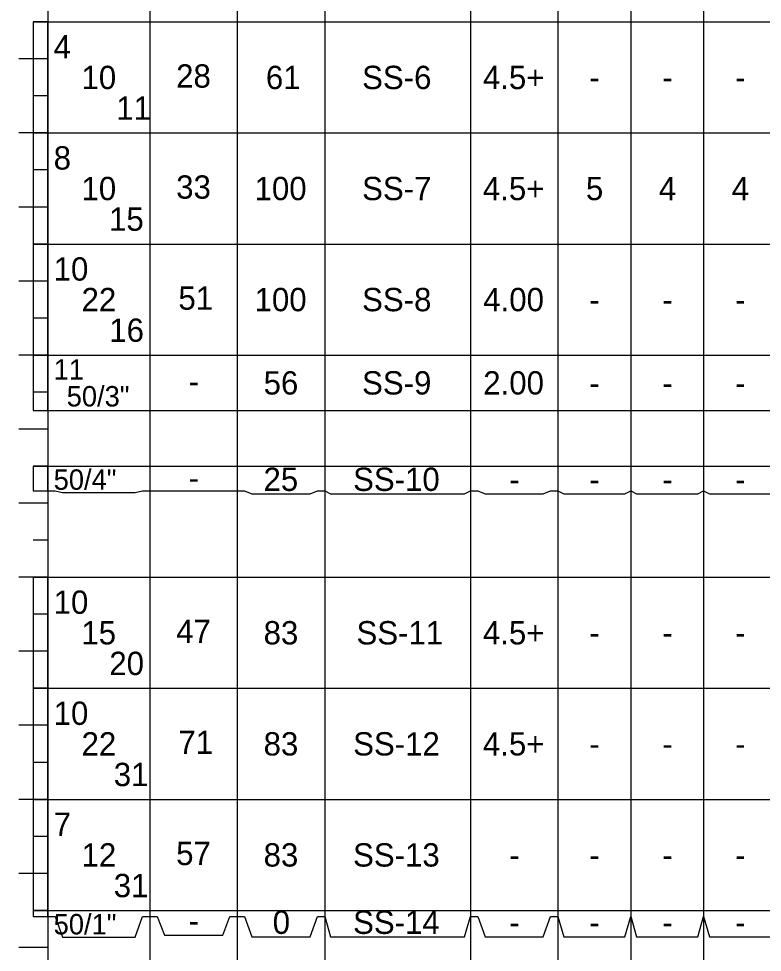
# Model space of a CAD drawing. Extents: x 0 to 0.833, y -0.323 to 0.608.
# Drawn here: x 0.4042 to 0.6168, y 0.0833 to 0.3502 of the extents above; entities that cross this region are included whole.
import ezdxf

# ---------------------------------------------------------------- set-up
doc = ezdxf.new("R2010")
doc.units = 0

msp = doc.modelspace()

# ---------------------------------------------------------------- linework, layer by layer
for points in [[(0.4125, 0.55417), (0.4125, -0.28575)], [(0.4125, 0.55417), (0.4125, -0.28575)], [(0.44167, 0.55417), (0.44167, -0.28575)], [(0.46667, 0.55417), (0.46667, -0.28575)], [(0.49167, 0.55417), (0.49167, -0.28575)], [(0.53333, 0.55417), (0.53333, -0.28575)], [(0.55833, 0.55417), (0.55833, -0.28575)], [(0.57917, 0.54167), (0.57917, -0.28575)], [(0.6, 0.54167), (0.6, -0.28575)], [(0.40833, 0.34925), (0.40833, 0.3175)], [(0.40833, 0.34925), (0.4125, 0.34925)], [(0.4125, 0.34925), (0.40833, 0.34925)], [(0.4125, 0.34925), (0.44167, 0.34925)], [(0.44167, 0.34925), (0.46667, 0.34925)], [(0.46667, 0.34925), (0.49167, 0.34925)], [(0.49167, 0.34925), (0.53333, 0.34925)], [(0.53333, 0.34925), (0.55833, 0.34925)], [(0.55833, 0.34925), (0.57917, 0.34925)], [(0.57917, 0.34925), (0.6, 0.34925)], [(0.6, 0.34925), (0.62083, 0.34925)], [(0.4125, 0.33867), (0.40417, 0.33867)], [(0.4125, 0.33867), (0.40833, 0.33867)], [(0.4125, 0.32808), (0.40833, 0.32808)], [(0.4125, 0.3175), (0.40417, 0.3175)], [(0.40833, 0.3175), (0.4125, 0.3175)], [(0.40833, 0.3175), (0.40833, 0.28575)], [(0.40833, 0.3175), (0.4125, 0.3175)], [(0.4125, 0.3175), (0.40833, 0.3175)], [(0.4125, 0.3175), (0.44167, 0.3175)], [(0.44167, 0.3175), (0.46667, 0.3175)], [(0.46667, 0.3175), (0.49167, 0.3175)], [(0.49167, 0.3175), (0.53333, 0.3175)], [(0.53333, 0.3175), (0.55833, 0.3175)], [(0.55833, 0.3175), (0.57917, 0.3175)], [(0.57917, 0.3175), (0.6, 0.3175)], [(0.6, 0.3175), (0.62083, 0.3175)], [(0.4125, 0.30692), (0.40833, 0.30692)], [(0.4125, 0.29633), (0.40417, 0.29633)], [(0.4125, 0.29633), (0.40833, 0.29633)], [(0.40833, 0.28575), (0.4125, 0.28575)], [(0.40833, 0.28575), (0.40833, 0.254)], [(0.40833, 0.28575), (0.4125, 0.28575)], [(0.4125, 0.28575), (0.40833, 0.28575)], [(0.4125, 0.28575), (0.44167, 0.28575)], [(0.44167, 0.28575), (0.46667, 0.28575)], [(0.46667, 0.28575), (0.49167, 0.28575)], [(0.49167, 0.28575), (0.53333, 0.28575)], [(0.53333, 0.28575), (0.55833, 0.28575)], [(0.55833, 0.28575), (0.57917, 0.28575)], [(0.57917, 0.28575), (0.6, 0.28575)], [(0.6, 0.28575), (0.62083, 0.28575)], [(0.4125, 0.27517), (0.40417, 0.27517)], [(0.4125, 0.27517), (0.40833, 0.27517)], [(0.4125, 0.26458), (0.40833, 0.26458)], [(0.4125, 0.254), (0.40417, 0.254)], [(0.40833, 0.254), (0.4125, 0.254)], [(0.40833, 0.254), (0.40833, 0.23812)], [(0.40833, 0.254), (0.4125, 0.254)], [(0.4125, 0.254), (0.40833, 0.254)], [(0.4125, 0.254), (0.44167, 0.254)], [(0.44167, 0.254), (0.46667, 0.254)], [(0.46667, 0.254), (0.49167, 0.254)], [(0.49167, 0.254), (0.53333, 0.254)], [(0.53333, 0.254), (0.55833, 0.254)], [(0.55833, 0.254), (0.57917, 0.254)], [(0.57917, 0.254), (0.6, 0.254)], [(0.6, 0.254), (0.62083, 0.254)], [(0.4125, 0.24342), (0.40833, 0.24342)], [(0.40833, 0.23812), (0.4125, 0.23812)], [(0.4125, 0.23812), (0.44167, 0.23812)], [(0.44167, 0.23812), (0.46667, 0.23812)], [(0.46667, 0.23812), (0.49167, 0.23812)], [(0.49167, 0.23812), (0.53333, 0.23812)], [(0.53333, 0.23812), (0.55833, 0.23812)], [(0.55833, 0.23812), (0.57917, 0.23812)], [(0.57917, 0.23812), (0.6, 0.23812)], [(0.6, 0.23812), (0.62083, 0.23812)], [(0.4125, 0.23283), (0.40417, 0.23283)], [(0.4125, 0.23283), (0.40833, 0.23283)], [(0.40833, 0.22225), (0.40833, 0.21519)], [(0.40833, 0.22225), (0.4125, 0.22225)], [(0.4125, 0.22225), (0.40833, 0.22225)], [(0.4125, 0.22225), (0.44167, 0.22225)], [(0.44167, 0.22225), (0.46667, 0.22225)], [(0.46667, 0.22225), (0.49167, 0.22225)], [(0.49167, 0.22225), (0.53333, 0.22225)], [(0.53333, 0.22225), (0.55833, 0.22225)], [(0.55833, 0.22225), (0.57917, 0.22225)], [(0.57917, 0.22225), (0.6, 0.22225)], [(0.6, 0.22225), (0.62083, 0.22225)], [(0.40833, 0.21519), (0.4125, 0.21519)], [(0.4125, 0.21519), (0.41458, 0.21519), (0.41667, 0.2147), (0.4375, 0.2147), (0.43958, 0.21519), (0.44167, 0.21519)], [(0.44167, 0.21519), (0.46667, 0.21519)], [(0.46667, 0.21519), (0.46875, 0.21519), (0.47083, 0.21437), (0.4875, 0.21437), (0.48958, 0.21519), (0.49167, 0.21519)], [(0.49167, 0.21519), (0.49333, 0.21437), (0.53167, 0.21437), (0.53333, 0.21519)], [(0.53333, 0.21519), (0.53542, 0.21519), (0.5375, 0.21437), (0.55417, 0.21437), (0.55625, 0.21519), (0.55833, 0.21519)], [(0.55833, 0.21519), (0.56, 0.21437), (0.5775, 0.21437), (0.57917, 0.21519)], [(0.57917, 0.21519), (0.58083, 0.21437), (0.59833, 0.21437), (0.6, 0.21519)], [(0.6, 0.21519), (0.60167, 0.21437), (0.61917, 0.21437), (0.62083, 0.21519)], [(0.4125, 0.21167), (0.40417, 0.21167)], [(0.4125, 0.21167), (0.40833, 0.21167)], [(0.4125, 0.20108), (0.40833, 0.20108)], [(0.4125, 0.1905), (0.40417, 0.1905)], [(0.40833, 0.1905), (0.40833, 0.15875)], [(0.40833, 0.1905), (0.4125, 0.1905)], [(0.4125, 0.1905), (0.40833, 0.1905)], [(0.4125, 0.1905), (0.44167, 0.1905)], [(0.44167, 0.1905), (0.46667, 0.1905)], [(0.46667, 0.1905), (0.49167, 0.1905)], [(0.49167, 0.1905), (0.53333, 0.1905)], [(0.53333, 0.1905), (0.55833, 0.1905)], [(0.55833, 0.1905), (0.57917, 0.1905)], [(0.57917, 0.1905), (0.6, 0.1905)], [(0.6, 0.1905), (0.62083, 0.1905)], [(0.4125, 0.17992), (0.40833, 0.17992)], [(0.4125, 0.16933), (0.40417, 0.16933)], [(0.4125, 0.16933), (0.40833, 0.16933)], [(0.40833, 0.15875), (0.4125, 0.15875)], [(0.40833, 0.15875), (0.40833, 0.127)], [(0.40833, 0.15875), (0.4125, 0.15875)], [(0.4125, 0.15875), (0.40833, 0.15875)], [(0.4125, 0.15875), (0.44167, 0.15875)], [(0.44167, 0.15875), (0.46667, 0.15875)], [(0.46667, 0.15875), (0.49167, 0.15875)], [(0.49167, 0.15875), (0.53333, 0.15875)], [(0.53333, 0.15875), (0.55833, 0.15875)], [(0.55833, 0.15875), (0.57917, 0.15875)], [(0.57917, 0.15875), (0.6, 0.15875)], [(0.6, 0.15875), (0.62083, 0.15875)], [(0.4125, 0.14817), (0.40417, 0.14817)], [(0.4125, 0.14817), (0.40833, 0.14817)], [(0.4125, 0.13758), (0.40833, 0.13758)], [(0.4125, 0.127), (0.40417, 0.127)], [(0.40833, 0.127), (0.4125, 0.127)], [(0.40833, 0.127), (0.40833, 0.09525)], [(0.40833, 0.127), (0.4125, 0.127)], [(0.4125, 0.127), (0.40833, 0.127)], [(0.4125, 0.127), (0.44167, 0.127)], [(0.44167, 0.127), (0.46667, 0.127)], [(0.46667, 0.127), (0.49167, 0.127)], [(0.49167, 0.127), (0.53333, 0.127)], [(0.53333, 0.127), (0.55833, 0.127)], [(0.55833, 0.127), (0.57917, 0.127)], [(0.57917, 0.127), (0.6, 0.127)], [(0.6, 0.127), (0.62083, 0.127)], [(0.4125, 0.11642), (0.40833, 0.11642)], [(0.4125, 0.10583), (0.40417, 0.10583)], [(0.4125, 0.10583), (0.40833, 0.10583)], [(0.40833, 0.09525), (0.4125, 0.09525)], [(0.40833, 0.09525), (0.40833, 0.09349)], [(0.40833, 0.09525), (0.4125, 0.09525)], [(0.4125, 0.09525), (0.40833, 0.09525)], [(0.40833, 0.09349), (0.4125, 0.09349)], [(0.4125, 0.09525), (0.44167, 0.09525)], [(0.4125, 0.09349), (0.41458, 0.09349), (0.41667, 0.08759), (0.4375, 0.08759), (0.43958, 0.09349), (0.44167, 0.09349)], [(0.44167, 0.09525), (0.46667, 0.09525)], [(0.44167, 0.09349), (0.44375, 0.09349), (0.44583, 0.08817), (0.4625, 0.08817), (0.46458, 0.09349), (0.46667, 0.09349)], [(0.46667, 0.09525), (0.49167, 0.09525)], [(0.46667, 0.09349), (0.46875, 0.09349), (0.47083, 0.08775), (0.4875, 0.08775), (0.48958, 0.09349), (0.49167, 0.09349)], [(0.49167, 0.09525), (0.53333, 0.09525)], [(0.49167, 0.09349), (0.49333, 0.08775), (0.53167, 0.08775), (0.53333, 0.09349)], [(0.53333, 0.09525), (0.55833, 0.09525)], [(0.53333, 0.09349), (0.53542, 0.09349), (0.5375, 0.08775), (0.55417, 0.08775), (0.55625, 0.09349), (0.55833, 0.09349)], [(0.55833, 0.09525), (0.57917, 0.09525)], [(0.55833, 0.09349), (0.56, 0.08775), (0.5775, 0.08775), (0.57917, 0.09349)], [(0.57917, 0.09525), (0.6, 0.09525)], [(0.57917, 0.09349), (0.58083, 0.08775), (0.59833, 0.08775), (0.6, 0.09349)], [(0.6, 0.09525), (0.62083, 0.09525)], [(0.6, 0.09349), (0.60167, 0.08775), (0.61917, 0.08775), (0.62083, 0.09349)], [(0.4125, 0.08467), (0.40417, 0.08467)], [(0.4125, 0.08467), (0.40833, 0.08467)]]:
    msp.add_lwpolyline(points)
for points in [[(0.40833, 0.3175), (0.4125, 0.3175), (0.4125, 0.34925), (0.40833, 0.34925)], [(0.40833, 0.28575), (0.4125, 0.28575), (0.4125, 0.3175), (0.40833, 0.3175)], [(0.40833, 0.254), (0.4125, 0.254), (0.4125, 0.28575), (0.40833, 0.28575)], [(0.40833, 0.23812), (0.4125, 0.23812), (0.4125, 0.254), (0.40833, 0.254)], [(0.40833, 0.21519), (0.4125, 0.21519), (0.4125, 0.22225), (0.40833, 0.22225)], [(0.40833, 0.15875), (0.4125, 0.15875), (0.4125, 0.1905), (0.40833, 0.1905)], [(0.40833, 0.127), (0.4125, 0.127), (0.4125, 0.15875), (0.40833, 0.15875)], [(0.40833, 0.09525), (0.4125, 0.09525), (0.4125, 0.127), (0.40833, 0.127)], [(0.40833, 0.09349), (0.4125, 0.09349), (0.4125, 0.09525), (0.40833, 0.09525)]]:
    msp.add_lwpolyline(points, close=True)

# ---------------------------------------------------------------- texts
for s, height, p in [('4', 0.00667, (0.41417, 0.33879)), ('10', 0.006667, (0.42213, 0.33004)), ('28', 0.006667, (0.44919, 0.33046)), ('61', 0.006667, (0.47484, 0.33004)), ('SS-6', 0.006667, (0.50236, 0.33004)), ('4.5+', 0.006667, (0.5369, 0.33004)), ('-', 0.00667, (0.56734, 0.33004)), ('-', 0.00667, (0.58818, 0.33004)), ('-', 0.00667, (0.60901, 0.33004)), ('11', 0.006667, (0.43205, 0.32129)), ('8', 0.00667, (0.41417, 0.30704)), ('10', 0.006667, (0.42213, 0.29829)), ('33', 0.006667, (0.4492, 0.29871)), ('100', 0.006667, (0.47162, 0.29829)), ('SS-7', 0.006667, (0.50236, 0.29829)), ('4.5+', 0.006667, (0.5369, 0.29829)), ('5', 0.00667, (0.56635, 0.29829)), ('4', 0.00667, (0.58722, 0.29829)), ('4', 0.00667, (0.60805, 0.29829)), ('15', 0.006667, (0.43001, 0.28954)), ('10', 0.006667, (0.41417, 0.27529)), ('22', 0.006667, (0.42215, 0.26654)), ('51', 0.006667, (0.44984, 0.26696)), ('100', 0.006667, (0.47162, 0.26654)), ('SS-8', 0.006667, (0.50235, 0.26654)), ('4.00', 0.006667, (0.537, 0.26654)), ('-', 0.00667, (0.56734, 0.26654)), ('-', 0.00667, (0.58818, 0.26654)), ('-', 0.00667, (0.60901, 0.26654)), ('16', 0.006667, (0.43007, 0.25779)), ('11', 0.005833, (0.41417, 0.24697)), ('56', 0.006667, (0.4742, 0.24273)), ('SS-9', 0.006667, (0.50235, 0.24273)), ('2.00', 0.006667, (0.537, 0.24273)), ('-', 0.00667, (0.45276, 0.24315)), ('-', 0.00667, (0.56734, 0.24273)), ('-', 0.00667, (0.58818, 0.24273)), ('-', 0.00667, (0.60901, 0.24273)), ('50/3"', 0.005833, (0.4179, 0.23932)), ('50/4"', 0.005833, (0.41417, 0.2155)), ('25', 0.006667, (0.47417, 0.21517)), ('SS-10', 0.006667, (0.49978, 0.21517)), ('-', 0.00667, (0.45276, 0.21558)), ('-', 0.00667, (0.54443, 0.21517)), ('-', 0.00667, (0.56734, 0.21517)), ('-', 0.00667, (0.58818, 0.21517)), ('-', 0.00667, (0.60901, 0.21517)), ('10', 0.006667, (0.41417, 0.18004)), ('15', 0.006667, (0.42209, 0.17129)), ('47', 0.006667, (0.4492, 0.17171)), ('83', 0.006667, (0.4742, 0.17129)), ('SS-11', 0.006667, (0.50076, 0.17129)), ('4.5+', 0.006667, (0.5369, 0.17129)), ('-', 0.00667, (0.56734, 0.17129)), ('-', 0.00667, (0.58818, 0.17129)), ('-', 0.00667, (0.60901, 0.17129)), ('20', 0.006667, (0.43009, 0.16254)), ('10', 0.006667, (0.41417, 0.14829)), ('22', 0.006667, (0.42215, 0.13954)), ('71', 0.006667, (0.44984, 0.13996)), ('83', 0.006667, (0.4742, 0.13954)), ('SS-12', 0.006667, (0.4998, 0.13954)), ('4.5+', 0.006667, (0.5369, 0.13954)), ('-', 0.00667, (0.56734, 0.13954)), ('-', 0.00667, (0.58818, 0.13954)), ('-', 0.00667, (0.60901, 0.13954)), ('31', 0.006667, (0.43136, 0.13079)), ('7', 0.00667, (0.41417, 0.11654)), ('57', 0.006667, (0.4492, 0.10821)), ('12', 0.006667, (0.42215, 0.10779)), ('83', 0.006667, (0.4742, 0.10779)), ('SS-13', 0.006667, (0.49977, 0.10779)), ('-', 0.00667, (0.54443, 0.10779)), ('-', 0.00667, (0.56734, 0.10779)), ('-', 0.00667, (0.58818, 0.10779)), ('-', 0.00667, (0.60901, 0.10779)), ('31', 0.006667, (0.43136, 0.09904)), ('50/1"', 0.005833, (0.41417, 0.0884)), ('0', 0.00667, (0.4768, 0.08854)), ('SS-14', 0.006667, (0.49978, 0.08854)), ('-', 0.00667, (0.45276, 0.08896)), ('-', 0.00667, (0.54443, 0.08854)), ('-', 0.00667, (0.56734, 0.08854)), ('-', 0.00667, (0.58818, 0.08854)), ('-', 0.00667, (0.60901, 0.08854))]:
    msp.add_text(s, height=height).set_placement(p)

doc.saveas('drawing.dxf')
